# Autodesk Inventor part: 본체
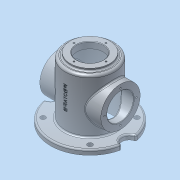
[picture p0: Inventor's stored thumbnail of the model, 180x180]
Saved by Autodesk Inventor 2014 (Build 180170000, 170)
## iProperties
Created: 2018-04
Part Number: 본체
Material: 알루미늄 6061
Document SubType Name: Modeling
Designer: net
Density: 2.71 g/cm^3
Appearance: 알루미늄 - 평지
Mass: 1151.3 g
Surface Area: 1200.36 cm^2
Volume: 424.833 cm^3
Author: net
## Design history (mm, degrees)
sketch "스케치1"
  geometry: L1 (0, 0)-(0, 140); L2 (50, 0)-(50, 8); L3 (50, 8)-(80, 8); L4 (80, 8)-(80, 18); L5 (80, 18)-(50, 18); L6 (50, 18)-(50, 128); L7 (50, 128)-(40, 128); L8 (27, 133)-(27, 120); L9 (27, 120)-(45, 120); L10 (45, 120)-(45, 0); L11 (40, 128)-(40, 133); L12 (40, 133)-(27, 133); L13 (45, 0)-(50, 0)
  constraints: 26 end point, 4 horizontal, 4 parallel, 2 perpendicular, 1 collinear, 1 horizontal alignment, 1 vertical
  dimensions: "d0" = 140 distance of L1.start L1.end; "d1" = 54 diameter of L8 L1; "d3" = 100 diameter of L6.end L1; "d5" = 8 distance of L2.start L2.end; "d6" = 100 diameter of L2 L1; "d7" = 10 distance of L3.end L4.end; "d8" = 160 diameter of L4 L1; "d11" = 13 distance of L8.start L8.end; "d13" = 90 diameter of L10 L1; "d14" = 80 diameter of L11 L1; "d15" = 133 vertical distance of L2.start L11.end; "d16" = 110 distance from line of L6.end L5
revolve "회전1" sketch "스케치1" stored, may be unused: angle "d17" = 90 deg
node "작업 평면1"
sketch "스케치2"
  geometry: L1 (0, 50)-(0, -50) reference; C1 r 40 at (68, 0); 2 further points
  constraints: 1 centre point, 1 horizontal alignment, 1 midpoint
  dimensions: "d19" = 68 distance from line of C1.centre L1; "d20" = 80 diameter of C1
extrude "돌출1" join sketch "스케치2" stored distance "d21" = 10; taper "d22" = 0 deg
sketch "스케치3"
  geometry: C1 r 40 at (0, 0) reference; C2 r 27 at (0, 0); 1 further point
  constraints: 1 centre point, 1 coincident
  dimensions: "d23" = 54 diameter of C2
extrude "돌출2" cut sketch "스케치3" stored distance "d24" = 0; taper "d25" = 0 deg
sketch "스케치4"
  geometry: C1 r 27 at (0, 0) reference; 2 further points
  constraints: 1 vertical alignment
  dimensions: "d26" = 32.5 distance of C1.centre point (0, 32.5)
hole "구멍1" sketch "스케치4" at (0, 32.5) diameter "d27" = 3.242; stored, may be unused: countersink angle "d31" = 90 deg, drill point angle "d33" = 118 deg; dims "d28" = 8, "d29" = 4, "d30" = 2, "d32" = 10
sketch "스케치5"
  geometry: 2 further points
  constraints: 1 vertical alignment
  dimensions: "d37" = 32.5 distance of point (0, 0) point (0, 32.5)
hole "구멍2" sketch "스케치5" at (0, 32.5) diameter "d38" = 3.242; stored, may be unused: countersink angle "d42" = 90 deg, drill point angle "d44" = 118 deg; dims "d39" = 8, "d40" = 4, "d41" = 2, "d43" = 10
fillet "모깎기1" dims "d48" = 3
chamfer "모따기1" distance "d49" = 1; stored, may be unused: second distance "d50" = 2, angle "d51" = 45 deg
chamfer "모따기2" distance "d52" = 1; stored, may be unused: second distance "d53" = 2, angle "d54" = 45 deg
fillet "모깎기2" dims "d55" = 3
fillet "모깎기3" dims "d56" = 3
fillet "모깎기4" dims "d57" = 3
fillet "모깎기5" dims "d58" = 5
sketch "스케치6"
  geometry: C1 r 15 at (-80, 0); C2 r 15 at (80, 0); A1 r 80 centre (0, 0) between (-80, 0) and (80, 0) reference; 1 further point
  constraints: 2 centre point, 2 horizontal alignment, 2 point on circle
  dimensions: "d59" = 30 diameter of C1; "d60" = 30 diameter of C2
extrude "돌출3" cut sketch "스케치6" distance "d61" = 10; taper "d62" = 0 deg
sketch "스케치7"
  geometry: L1 (0, 0)-(0, 73.406); L2 (-47.73, 47.73)-(0, 0)
  constraints: 4 end point, 1 vertical
  dimensions: "d63" = 45 deg angle of L1 L2; "d64" = 67.5 distance of L1.start L2.start
hole "구멍3" sketch "스케치7" at (-47.73, 47.73) diameter "d65" = 10; stored, may be unused: countersink angle "d69" = 90 deg, drill point angle "d71" = 118 deg; dims "d66" = 8, "d67" = 4, "d68" = 2, "d70" = 10
fillet "모깎기6" dims "d75" = 3
node "작업 평면2"
sketch "스케치8"
  geometry: L1 (-77.955, 8)-(77.955, 8) reference; 2 further points
  constraints: 1 vertical alignment, 1 other
  dimensions: "d81" = 70 distance from line of point (0, 78) L1
fillet "모깎기7" dims "d78" = 3
feature "엠보싱1" dims "d79" = 0.5, "d80" = 0
node "솔리드1"
mirror "대칭1"
pattern_circular "원형 패턴1" dims angle "d35" = 360 deg
mirror "대칭2"
pattern_circular "원형 패턴2" dims angle "d46" = 360 deg
pattern_circular "원형 패턴3" dims angle "d73" = 360 deg
other parameters: "d18" = 62, "d76" = 75
